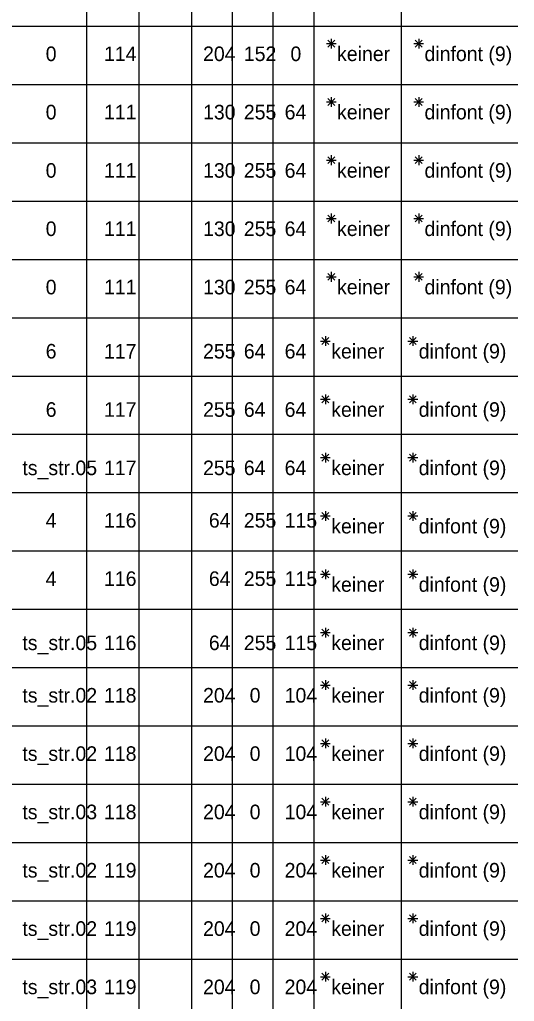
# Model space of a CAD drawing. Extents: x -29 to 48, y -113 to 16.
# Drawn here: x 23.45 to 31.94, y -30.72 to -13.89 of the extents above; entities that cross this region are included whole.
import ezdxf

# ---------------------------------------------------------------- set-up
doc = ezdxf.new("R2010")
doc.units = 0
doc.layers.add('Default', color=7, linetype='Continuous')

msp = doc.modelspace()

# ---------------------------------------------------------------- linework, layer by layer
at = {"layer": 'Default'}
for p, q in [((24.6, -0.7), (24.6, -89)), ((25.5, -0.7), (25.5, -89)), ((26.4, -0.7), (26.4, -89)), ((28.5, -0.7), (28.5, -96)), ((30, -0.7), (30, -96)), ((27.1, -1.5), (27.1, -89)), ((27.8, -1.5), (27.8, -89)), ((0, -14), (32, -14)), ((28.716, -14.3), (28.884, -14.3)), ((28.741, -14.241), (28.859, -14.359)), ((28.859, -14.241), (28.741, -14.359)), ((28.8, -14.216), (28.8, -14.384)), ((30.216, -14.3), (30.384, -14.3)), ((30.241, -14.241), (30.359, -14.359)), ((30.359, -14.241), (30.241, -14.359)), ((30.3, -14.216), (30.3, -14.384)), ((0, -15), (32, -15)), ((28.716, -15.3), (28.884, -15.3)), ((28.741, -15.241), (28.859, -15.359)), ((28.859, -15.241), (28.741, -15.359)), ((28.8, -15.216), (28.8, -15.384)), ((30.216, -15.3), (30.384, -15.3)), ((30.241, -15.241), (30.359, -15.359)), ((30.359, -15.241), (30.241, -15.359)), ((30.3, -15.216), (30.3, -15.384)), ((0, -16), (32, -16)), ((28.716, -16.3), (28.884, -16.3)), ((28.741, -16.241), (28.859, -16.359)), ((28.859, -16.241), (28.741, -16.359)), ((28.8, -16.216), (28.8, -16.384)), ((30.216, -16.3), (30.384, -16.3)), ((30.241, -16.241), (30.359, -16.359)), ((30.359, -16.241), (30.241, -16.359)), ((30.3, -16.216), (30.3, -16.384)), ((0, -17), (32, -17)), ((28.716, -17.3), (28.884, -17.3)), ((28.741, -17.241), (28.859, -17.359)), ((28.859, -17.241), (28.741, -17.359)), ((28.8, -17.216), (28.8, -17.384)), ((30.216, -17.3), (30.384, -17.3)), ((30.241, -17.241), (30.359, -17.359)), ((30.359, -17.241), (30.241, -17.359)), ((30.3, -17.216), (30.3, -17.384)), ((0, -18), (32, -18)), ((28.716, -18.3), (28.884, -18.3)), ((28.741, -18.241), (28.859, -18.359)), ((28.859, -18.241), (28.741, -18.359)), ((28.8, -18.216), (28.8, -18.384)), ((30.216, -18.3), (30.384, -18.3)), ((30.241, -18.241), (30.359, -18.359)), ((30.359, -18.241), (30.241, -18.359)), ((30.3, -18.216), (30.3, -18.384)), ((0, -19), (32, -19)), ((28.641, -19.341), (28.759, -19.459)), ((28.759, -19.341), (28.641, -19.459)), ((28.7, -19.316), (28.7, -19.484)), ((30.141, -19.341), (30.259, -19.459)), ((30.259, -19.341), (30.141, -19.459)), ((30.2, -19.316), (30.2, -19.484)), ((28.616, -19.4), (28.784, -19.4)), ((30.116, -19.4), (30.284, -19.4)), ((0, -20), (32, -20)), ((28.641, -20.341), (28.759, -20.459)), ((28.759, -20.341), (28.641, -20.459)), ((28.7, -20.316), (28.7, -20.484)), ((30.141, -20.341), (30.259, -20.459)), ((30.259, -20.341), (30.141, -20.459)), ((30.2, -20.316), (30.2, -20.484)), ((28.616, -20.4), (28.784, -20.4)), ((30.116, -20.4), (30.284, -20.4)), ((0, -21), (32, -21)), ((28.641, -21.341), (28.759, -21.459)), ((28.759, -21.341), (28.641, -21.459)), ((28.7, -21.316), (28.7, -21.484)), ((30.141, -21.341), (30.259, -21.459)), ((30.259, -21.341), (30.141, -21.459)), ((30.2, -21.316), (30.2, -21.484)), ((28.616, -21.4), (28.784, -21.4)), ((30.116, -21.4), (30.284, -21.4)), ((0, -22), (32, -22)), ((28.641, -22.341), (28.759, -22.459)), ((28.759, -22.341), (28.641, -22.459)), ((28.7, -22.316), (28.7, -22.484)), ((30.141, -22.341), (30.259, -22.459)), ((30.259, -22.341), (30.141, -22.459)), ((30.2, -22.316), (30.2, -22.484)), ((28.616, -22.4), (28.784, -22.4)), ((30.116, -22.4), (30.284, -22.4)), ((0, -23), (32, -23)), ((28.641, -23.341), (28.759, -23.459)), ((28.759, -23.341), (28.641, -23.459)), ((28.7, -23.316), (28.7, -23.484)), ((30.141, -23.341), (30.259, -23.459)), ((30.259, -23.341), (30.141, -23.459)), ((30.2, -23.316), (30.2, -23.484)), ((28.616, -23.4), (28.784, -23.4)), ((30.116, -23.4), (30.284, -23.4)), ((0, -24), (32, -24)), ((28.616, -24.4), (28.784, -24.4)), ((28.641, -24.341), (28.759, -24.459)), ((28.759, -24.341), (28.641, -24.459)), ((28.7, -24.316), (28.7, -24.484)), ((30.116, -24.4), (30.284, -24.4)), ((30.141, -24.341), (30.259, -24.459)), ((30.259, -24.341), (30.141, -24.459)), ((30.2, -24.316), (30.2, -24.484)), ((0, -25), (32, -25)), ((28.641, -25.241), (28.759, -25.359)), ((28.759, -25.241), (28.641, -25.359)), ((28.7, -25.216), (28.7, -25.384)), ((30.141, -25.241), (30.259, -25.359)), ((30.259, -25.241), (30.141, -25.359)), ((30.2, -25.216), (30.2, -25.384)), ((28.616, -25.3), (28.784, -25.3)), ((30.116, -25.3), (30.284, -25.3)), ((0, -26), (32, -26)), ((28.641, -26.241), (28.759, -26.359)), ((28.759, -26.241), (28.641, -26.359)), ((28.7, -26.216), (28.7, -26.384)), ((30.141, -26.241), (30.259, -26.359)), ((30.259, -26.241), (30.141, -26.359)), ((30.2, -26.216), (30.2, -26.384)), ((28.616, -26.3), (28.784, -26.3)), ((30.116, -26.3), (30.284, -26.3)), ((0, -27), (32, -27)), ((28.641, -27.241), (28.759, -27.359)), ((28.759, -27.241), (28.641, -27.359)), ((28.7, -27.216), (28.7, -27.384)), ((30.141, -27.241), (30.259, -27.359)), ((30.259, -27.241), (30.141, -27.359)), ((30.2, -27.216), (30.2, -27.384)), ((28.616, -27.3), (28.784, -27.3)), ((30.116, -27.3), (30.284, -27.3)), ((0, -28), (32, -28)), ((28.641, -28.241), (28.759, -28.359)), ((28.759, -28.241), (28.641, -28.359)), ((28.7, -28.216), (28.7, -28.384)), ((30.141, -28.241), (30.259, -28.359)), ((30.259, -28.241), (30.141, -28.359)), ((30.2, -28.216), (30.2, -28.384)), ((28.616, -28.3), (28.784, -28.3)), ((30.116, -28.3), (30.284, -28.3)), ((0, -29), (32, -29)), ((28.641, -29.241), (28.759, -29.359)), ((28.759, -29.241), (28.641, -29.359)), ((28.7, -29.216), (28.7, -29.384)), ((30.141, -29.241), (30.259, -29.359)), ((30.259, -29.241), (30.141, -29.359)), ((30.2, -29.216), (30.2, -29.384)), ((28.616, -29.3), (28.784, -29.3)), ((30.116, -29.3), (30.284, -29.3)), ((0, -30), (32, -30)), ((28.616, -30.3), (28.784, -30.3)), ((28.641, -30.241), (28.759, -30.359)), ((28.759, -30.241), (28.641, -30.359)), ((28.7, -30.216), (28.7, -30.384)), ((30.116, -30.3), (30.284, -30.3)), ((30.141, -30.241), (30.259, -30.359)), ((30.259, -30.241), (30.141, -30.359)), ((30.2, -30.216), (30.2, -30.384))]:
    msp.add_line(p, q, dxfattribs=at)

# ---------------------------------------------------------------- texts
for s, p in [('0', (23.9, -14.6)), ('114', (24.9, -14.6)), ('204', (26.6, -14.6)), ('152', (27.3, -14.6)), ('0', (28.1, -14.6)), ('keiner', (28.9, -14.6)), ('dinfont (9)', (30.4, -14.6)), ('0', (23.9, -15.6)), ('111', (24.9, -15.6)), ('130', (26.6, -15.6)), ('255', (27.3, -15.6)), ('64', (28, -15.6)), ('keiner', (28.9, -15.6)), ('dinfont (9)', (30.4, -15.6)), ('0', (23.9, -16.6)), ('111', (24.9, -16.6)), ('130', (26.6, -16.6)), ('255', (27.3, -16.6)), ('64', (28, -16.6)), ('keiner', (28.9, -16.6)), ('dinfont (9)', (30.4, -16.6)), ('keiner', (28.9, -17.6)), ('dinfont (9)', (30.4, -17.6)), ('0', (23.9, -17.6)), ('111', (24.9, -17.6)), ('130', (26.6, -17.6)), ('255', (27.3, -17.6)), ('64', (28, -17.6)), ('0', (23.9, -18.6)), ('130', (26.6, -18.6)), ('255', (27.3, -18.6)), ('64', (28, -18.6)), ('keiner', (28.9, -18.6)), ('dinfont (9)', (30.4, -18.6)), ('111', (24.9, -18.6)), ('6', (23.9, -19.7)), ('117', (24.9, -19.7)), ('255', (26.6, -19.7)), ('64', (27.3, -19.7)), ('64', (28, -19.7)), ('keiner', (28.8, -19.7)), ('dinfont (9)', (30.3, -19.7)), ('6', (23.9, -20.7)), ('117', (24.9, -20.7)), ('255', (26.6, -20.7)), ('64', (27.3, -20.7)), ('64', (28, -20.7)), ('keiner', (28.8, -20.7)), ('dinfont (9)', (30.3, -20.7)), ('ts_str.05', (23.5, -21.7)), ('117', (24.9, -21.7)), ('255', (26.6, -21.7)), ('64', (27.3, -21.7)), ('64', (28, -21.7)), ('keiner', (28.8, -21.7)), ('dinfont (9)', (30.3, -21.7)), ('4', (23.9, -22.6)), ('116', (24.9, -22.6)), ('64', (26.7, -22.6)), ('255', (27.3, -22.6)), ('115', (28, -22.6)), ('keiner', (28.8, -22.7)), ('dinfont (9)', (30.3, -22.7)), ('4', (23.9, -23.6)), ('116', (24.9, -23.6)), ('64', (26.7, -23.6)), ('255', (27.3, -23.6)), ('115', (28, -23.6)), ('keiner', (28.8, -23.7)), ('dinfont (9)', (30.3, -23.7)), ('ts_str.05', (23.5, -24.7)), ('116', (24.9, -24.7)), ('64', (26.7, -24.7)), ('255', (27.3, -24.7)), ('115', (28, -24.7)), ('keiner', (28.8, -24.7)), ('dinfont (9)', (30.3, -24.7)), ('ts_str.02', (23.5, -25.6)), ('118', (24.9, -25.6)), ('204', (26.6, -25.6)), ('0', (27.4, -25.6)), ('104', (28, -25.6)), ('keiner', (28.8, -25.6)), ('dinfont (9)', (30.3, -25.6)), ('ts_str.02', (23.5, -26.6)), ('118', (24.9, -26.6)), ('204', (26.6, -26.6)), ('0', (27.4, -26.6)), ('104', (28, -26.6)), ('keiner', (28.8, -26.6)), ('dinfont (9)', (30.3, -26.6)), ('ts_str.03', (23.5, -27.6)), ('118', (24.9, -27.6)), ('204', (26.6, -27.6)), ('0', (27.4, -27.6)), ('104', (28, -27.6)), ('keiner', (28.8, -27.6)), ('dinfont (9)', (30.3, -27.6)), ('ts_str.02', (23.5, -28.6)), ('119', (24.9, -28.6)), ('204', (26.6, -28.6)), ('0', (27.4, -28.6)), ('204', (28, -28.6)), ('keiner', (28.8, -28.6)), ('dinfont (9)', (30.3, -28.6)), ('ts_str.02', (23.5, -29.6)), ('119', (24.9, -29.6)), ('204', (26.6, -29.6)), ('0', (27.4, -29.6)), ('204', (28, -29.6)), ('keiner', (28.8, -29.6)), ('dinfont (9)', (30.3, -29.6)), ('ts_str.03', (23.5, -30.6)), ('119', (24.9, -30.6)), ('204', (26.6, -30.6)), ('0', (27.4, -30.6)), ('204', (28, -30.6)), ('keiner', (28.8, -30.6)), ('dinfont (9)', (30.3, -30.6))]:
    msp.add_text(s, height=0.25, dxfattribs=at).set_placement(p)

doc.saveas('drawing.dxf')
